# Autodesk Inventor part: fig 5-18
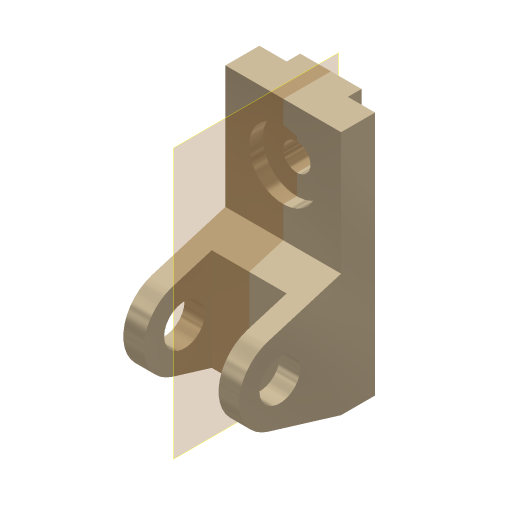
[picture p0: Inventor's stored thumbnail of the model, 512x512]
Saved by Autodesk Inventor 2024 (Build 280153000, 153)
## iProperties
Shininess: 65.0
Angle Display Precision: 2
Document Length Units: 11269
Document Angle Units: 11279
Document Time Units: 11290
Document Mass Units: 11283
Document Length Units Precision: 3
Document Angle Units Precision: 2
Compacted: False
Created: 2001-11
Part Number: fig 5-18
Document SubType Name: Modeling
Designer: Renu Muthoo
Density: 1 g/cm^3
Material: Generic
Appearance: Metal-Titanium (Polished)
Density: 0.0
Volumn: 0.0
Area: 0.0
PropertySet Name: Model Information
Control State: 0
Master: False
Checked Out: False
Author: Renu Muthoo
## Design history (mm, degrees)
sketch "Sketch2"
  geometry: L1 (33.257, 104.664)-(33.257, -75.336); L2 (33.257, -75.336)-(8.257, -75.336); L3 (8.257, -75.336)-(-45.451, -59.045); L4 (-45.451, -1.628)-(8.257, 14.664); L5 (8.257, 14.664)-(8.257, 104.664); L6 (8.257, 104.664)-(33.257, 104.664); C1 r 15 at (-36.743, -30.336); A1 r 30 centre (-36.743, -30.336) between (-45.451, -1.628) and (-45.451, -59.045)
  constraints: 12 end point, 2 centre point, 2 equal length, 2 parallel, 2 point on circle, 2 tangent, 1 coincident, 1 perpendicular, 1 vertical
  dimensions: "d0" = 180 distance of L1.start L1.end; "d1" = 30 radius of A1; "d2" = 25 distance of L5.end L1.start; "d3" = 45 distance from line of L2 A1.centre; "d4" = 70 distance from line of L1 A1.centre; "d5" = 30 diameter of C1
extrude "Extrusion1" new body sketch "Sketch2" distance "d6" = 85; taper "d7" = 0 deg
workplane "Work Plane1"
sketch "Sketch3"
  geometry: L1 (15, 62.364)-(70, 62.364); L2 (70, 62.364)-(70, -52.386); L3 (70, -52.386)-(15, -52.386); L4 (15, -52.386)-(15, 62.364); L5 (0, -45)-(0, -28.708) reference
  constraints: 8 end point, 2 parallel, 1 horizontal, 1 perpendicular
  dimensions: "d8" = 55 distance of L1.start L1.end; "d9" = 15 distance between parallel lines of L5 L4
extrude "Extrusion2" cut sketch "Sketch3" distance "d10" = 50; taper "d11" = 0 deg
sketch "Sketch4"
  geometry: L1 (0, 25)-(85, 25) reference; L2 (0, 0)-(0, 25) reference; L3 (20, 25)-(65, 25); L4 (65, 25)-(65, 35); L5 (65, 35)-(20, 35); L6 (20, 35)-(20, 25)
  constraints: 8 end point, 2 parallel, 1 horizontal, 1 perpendicular, 1 point on line
  dimensions: "d12" = 45 distance of L4.end L5.end; "d13" = 10 distance of L3.end L4.end; "d14" = 20 distance between parallel lines of L2 L6
extrude "Extrusion3" join sketch "Sketch4" stored distance "d15" = 50; taper "d16" = 0 deg
sketch "Sketch5"
  geometry: L1 (85, 0)-(85, 90) reference; L2 (0, 90)-(85, 90) reference; 1 further point
  dimensions: "d17" = 42 distance from line of L2 point (42.5, 48); "d18" = 42.5 distance from line of L1 point (42.5, 48)
hole "Hole1" sketch "Sketch5" diameter "d19" = 20; stored, may be unused: countersink angle "d23" = 82 deg, drill point angle "d25" = 118 deg; dims "d20" = 6, "d21" = 50, "d22" = 10, "d24" = 8
workplane "Work Plane9"
body "Solid1"
node "Sketch1"
